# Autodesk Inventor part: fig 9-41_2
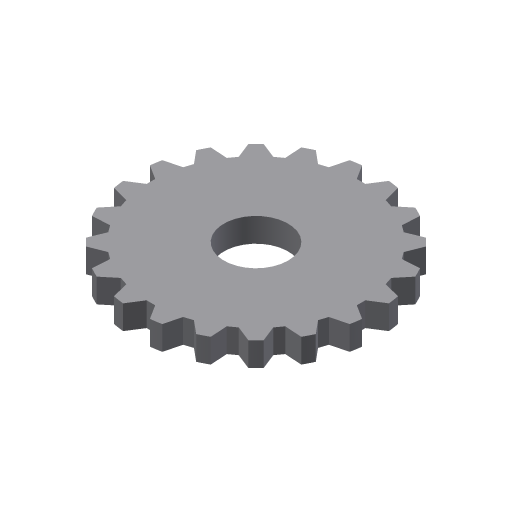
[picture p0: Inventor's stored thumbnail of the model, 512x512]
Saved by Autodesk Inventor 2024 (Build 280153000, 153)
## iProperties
Created: 2013-03
Part Number: fig 9-41_2
Material: Generic
Document SubType Name: Modeling
Designer: CADCIM
Density: 1 g/cm^3
Appearance: Default
Author: CADCIM
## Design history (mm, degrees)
sketch "Sketch1"
  geometry: C1 r 15 at (0, 0); C2 r 4 at (0, 0); 1 further point
  constraints: 2 centre point, 2 coincident
  dimensions: "d0" = 30 diameter of C1; "d2" = 8 diameter of C2
extrude "Extrusion1" new body sketch "Sketch1" distance "d3" = 3; taper "d4" = 0 deg
sketch "Sketch2"
  geometry: L1 (-1.675, 14.906)-(-0.536, 13.106); L2 (-0.536, 13.106)-(0.536, 13.106); L3 (0.536, 13.106)-(1.675, 14.906); L4 (0, 0)-(0, 16.254); C1 r 15 at (0, 0) reference; A1 r 15 centre (0, 0) between (1.675, 14.906) and (-1.675, 14.906); 2 further points
  constraints: 8 end point, 2 point on circle, 2 symmetric about line, 1 centre point, 1 coincident, 1 horizontal, 1 perpendicular
  dimensions: "d5" = 30 diameter of A1
extrude "Extrusion2" cut sketch "Sketch2" distance "d7" = 3; taper "d8" = 0 deg
body "Solid1"
pattern_circular "Circular Pattern1" dims angle "d10" = 360 deg
